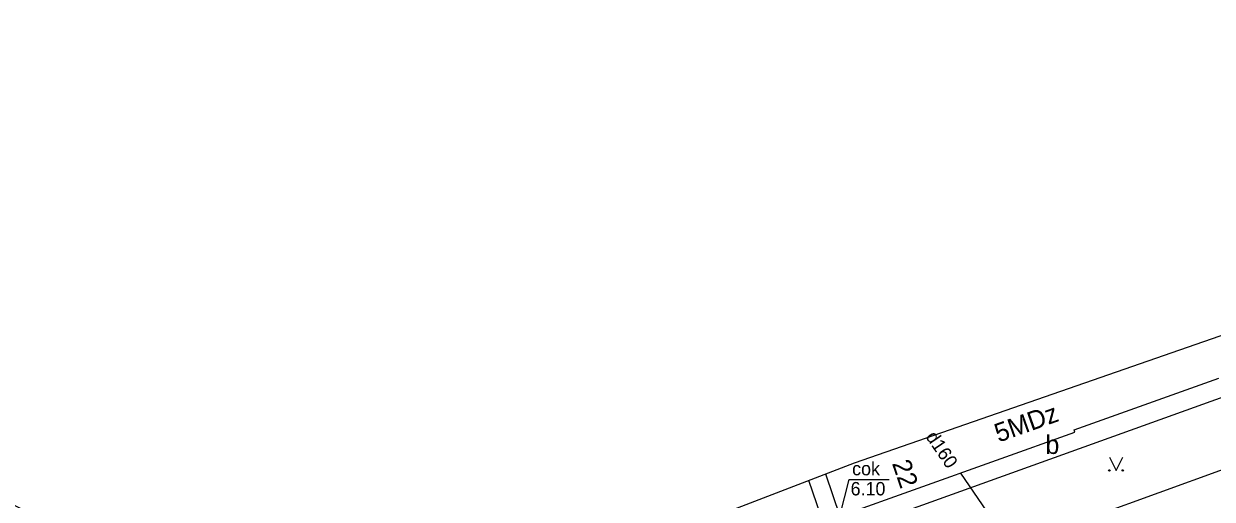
# Model space of a CAD drawing. Extents: x 519536 to 519949, y 326041 to 326519.
# Drawn here: x 519646.66 to 519691.1, y 326341.43 to 326359.19 of the extents above; entities that cross this region are included whole.
import ezdxf

# ---------------------------------------------------------------- set-up
doc = ezdxf.new("R2010")
doc.units = 0
for name, color, linetype in [('BUVE_COKL_####_####_#', 7, 'Continuous'), ('BUVE_EKAS_####_####_#', 7, 'Continuous'), ('BUVE_EKAS_ADRS_TKST_#', 7, 'Continuous'), ('BUVE_EKAS_RAKS_TKST_#', 7, 'Continuous'), ('CELI_CMAL_####_####_#', 7, 'Continuous'), ('CELI_CSEG_####_TKST_#', 7, 'Continuous'), ('RAMI_UZMR_####_####_#', 7, 'Continuous'), ('RELJ_HORZ_PAMT_####_#', 7, 'Continuous'), ('SKAN_VADP_PAST_####_#', 7, 'Continuous'), ('SKAN_VADP_PAST_TKST_#', 7, 'Continuous'), ('TERT_ELEM_####_####_#', 7, 'Continuous'), ('TERT_KRND_####_####_#', 7, 'Continuous')]:
    doc.layers.add(name, color=color, linetype=linetype)

msp = doc.modelspace()

# ---------------------------------------------------------------- linework, layer by layer
at = {"layer": 'BUVE_COKL_####_####_#'}
msp.add_lwpolyline([(519677.174, 326340.79), (519677.519, 326342.162), (519679.015, 326342.162)], dxfattribs=at)
at = {"layer": 'BUVE_EKAS_####_####_#'}
for p, q in [((519685.929, 326344.02), (519691.344, 326345.952)), ((519685.961, 326343.925), (519685.929, 326344.02)), ((519677.174, 326340.79), (519685.961, 326343.925)), ((519676.631, 326342.369), (519677.174, 326340.79))]:
    msp.add_line(p, q, dxfattribs=at)
at = {"layer": 'CELI_CMAL_####_####_#'}
for points in [[(519692.642, 326345.647), (519676.758, 326339.946)], [(519676.758, 326339.946), (519676.008, 326342.129)]]:
    msp.add_lwpolyline(points, dxfattribs=at)
at = {"layer": 'RAMI_UZMR_####_####_#'}
msp.add_lwpolyline([(519636.229, 326369.014), (519636.521, 326358.648), (519635.235, 326346.665), (519658.236, 326335.303), (519677.714, 326342.785), (519698.5, 326350)], dxfattribs=at)
at = {"layer": 'RELJ_HORZ_PAMT_####_#'}
msp.add_spline([(519699.928, 326341.912), (519699.913, 326341.841), (519699.705, 326341.121), (519699.557, 326340.762), (519699.376, 326340.403), (519698.841, 326339.569), (519698.219, 326338.867), (519697.492, 326338.302), (519697.083, 326338.073), (519696.64, 326337.88), (519694.817, 326337.31), (519694.363, 326337.207), (519693.909, 326337.115), (519693.452, 326337.035), (519692.993, 326336.972), (519692.537, 326336.924), (519692.08, 326336.885), (519691.624, 326336.86), (519691.167, 326336.852), (519690.71, 326336.858), (519690.253, 326336.873), (519689.339, 326336.936), (519688.505, 326337.019), (519687.672, 326337.105), (519686.541, 326337.23)], degree=3, dxfattribs=at)
at = {"layer": 'SKAN_VADP_PAST_####_#'}
msp.add_lwpolyline([(519683.5, 326339.756), (519681.695, 326342.403)], dxfattribs=at)
at = {"layer": 'TERT_ELEM_####_####_#'}
for p, q in [((519687.25, 326343), (519687.5, 326342.5)), ((519687.5, 326342.5), (519687.75, 326343))]:
    msp.add_line(p, q, dxfattribs=at)
for centre, radius in [((519687.25, 326342.5), 0.028), ((519687.75, 326342.5), 0.0263)]:
    msp.add_circle(centre, radius, dxfattribs=at)
at = {"layer": 'TERT_KRND_####_####_#'}
msp.add_lwpolyline([(519670.969, 326340.194), (519671.972, 326337.159), (519679.494, 326338.186), (519696.33, 326344.286)], dxfattribs=at)

# ---------------------------------------------------------------- texts
at = {"layer": 'BUVE_COKL_####_####_#'}
for s, p in [('cok', (519677.631, 326342.318)), ('6.10', (519677.574, 326341.568))]:
    msp.add_text(s, height=0.5, dxfattribs=at).set_placement(p)
at = {"layer": 'BUVE_EKAS_ADRS_TKST_#'}
msp.add_text('22', height=0.7, rotation=288.9814, dxfattribs=at).set_placement((519679.116, 326342.765))
at = {"layer": 'BUVE_EKAS_RAKS_TKST_#'}
msp.add_text('5MDz', height=0.7, rotation=19.6357, dxfattribs=at).set_placement((519683.107, 326343.538))
at = {"layer": 'CELI_CSEG_####_TKST_#'}
msp.add_text('b', height=0.7, dxfattribs=at).set_placement((519684.859, 326343.116))
at = {"layer": 'SKAN_VADP_PAST_TKST_#'}
msp.add_text('d160', height=0.5, rotation=304.2902, dxfattribs=at).set_placement((519680.362, 326343.757))

doc.saveas('drawing.dxf')
